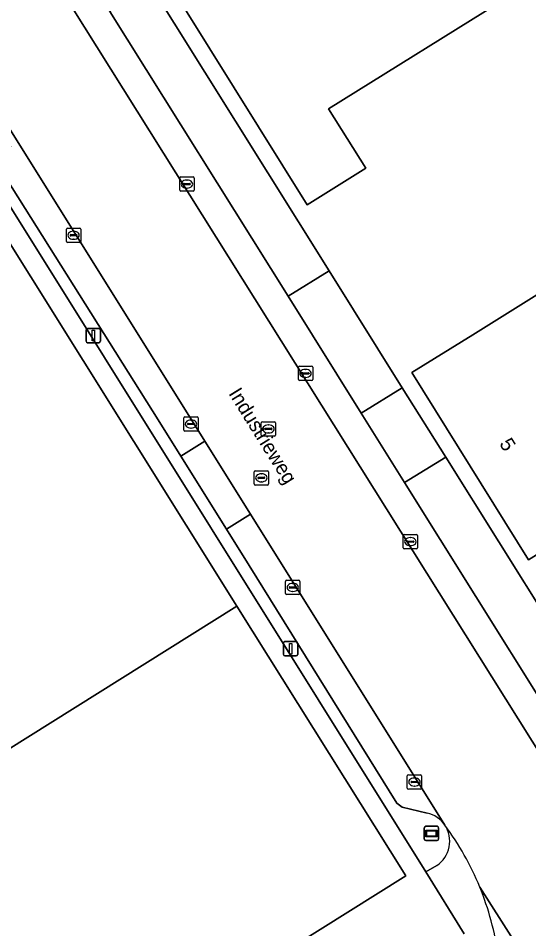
# Model space of a CAD drawing. Extents: x 158455 to 159797, y 387218 to 388672.
# Drawn here: x 158669.4 to 158705, y 387757.5 to 387821.1 of the extents above; entities that cross this region are included whole.
import ezdxf

# ---------------------------------------------------------------- set-up
doc = ezdxf.new("R2010")
doc.units = 0
for name, color, linetype in [('IMGEO_Erf', 7, 'Continuous'), ('IMGEO_Kolk', 7, 'Continuous'), ('IMGEO_Lichtmast', 7, 'Continuous'), ('IMGEO_Openbare_ruimte_label', 7, 'Continuous'), ('IMGEO_Pand', 7, 'Continuous'), ('IMGEO_Pand_nummerreeks', 7, 'Continuous'), ('IMGEO_Parkeervlak_open', 7, 'Continuous'), ('IMGEO_Rijbaan_lokaal_gesloten', 7, 'Continuous'), ('IMGEO_Rioolput', 7, 'Continuous'), ('IMGEO_Voetpad_open', 7, 'Continuous'), ('IMGEO_Wegwijzer', 7, 'Continuous')]:
    doc.layers.add(name, color=color, linetype=linetype)

msp = doc.modelspace()

# ---------------------------------------------------------------- linework, layer by layer
at = {"layer": 'IMGEO_Erf'}
for points in [[(158707.009, 387857.672), (158697.055, 387851.465), (158693.417, 387849.212), (158672.211, 387835.913), (158671.304, 387835.407), (158671.246, 387835.269), (158671.606, 387834.665), (158691.111, 387803.48), (158696.218, 387795.316), (158699.252, 387790.473), (158714.054, 387766.818), (158717.252, 387761.719), (158733.714, 387772.034), (158739.37, 387775.529), (158743.923, 387778.371), (158747.2, 387780.372), (158755.504, 387785.603)], [(158700.543, 387757.176), (158697.853, 387761.514), (158667.897, 387809.455), (158665.935, 387812.659), (158664.762, 387811.924), (158665.289, 387811.083), (158666.728, 387808.713), (158684.676, 387780.065), (158696.467, 387761.244), (158678.519, 387750)], [(158709.281, 387785.958), (158705.038, 387783.311), (158696.888, 387796.376), (158701.131, 387799.023), (158709.969, 387804.536)]]:
    msp.add_lwpolyline(points, dxfattribs=at)
msp.add_lwpolyline([(158694.061, 387848.221), (158704.182, 387854.586), (158709.488, 387846.148), (158713.329, 387848.544), (158722.022, 387834.609), (158708.006, 387825.866), (158703.715, 387823.19), (158703.941, 387822.828), (158691.073, 387814.801), (158693.667, 387810.644), (158689.585, 387808.098), (158672.704, 387835.159), (158689.655, 387845.732), (158689.781, 387845.53)], close=True, dxfattribs=at)
at = {"layer": 'IMGEO_Kolk'}
for p, q in [((158680.681, 387809.113), (158680.681, 387809.965)), ((158680.756, 387810.039), (158681.608, 387810.039)), ((158681.682, 387809.965), (158681.682, 387809.113)), ((158680.94, 387809.533), (158680.94, 387809.545)), ((158681.378, 387809.496), (158680.98, 387809.496)), ((158680.983, 387809.582), (158681.381, 387809.582)), ((158681.169, 387809.819), (158681.194, 387809.819)), ((158681.424, 387809.545), (158681.424, 387809.533)), ((158681.608, 387809.039), (158680.756, 387809.039)), ((158681.192, 387809.259), (158681.167, 387809.259)), ((158672.768, 387805.542), (158672.768, 387806.394)), ((158672.843, 387806.468), (158673.695, 387806.468)), ((158673.256, 387806.248), (158673.281, 387806.248)), ((158673.769, 387806.394), (158673.769, 387805.542)), ((158673.027, 387805.962), (158673.027, 387805.974)), ((158673.465, 387805.925), (158673.067, 387805.925)), ((158673.07, 387806.011), (158673.468, 387806.011)), ((158673.279, 387805.688), (158673.254, 387805.688)), ((158673.511, 387805.974), (158673.511, 387805.962)), ((158673.695, 387805.468), (158672.843, 387805.468)), ((158688.962, 387795.893), (158688.962, 387796.745)), ((158689.037, 387796.819), (158689.889, 387796.819)), ((158689.45, 387796.599), (158689.475, 387796.599)), ((158689.963, 387796.745), (158689.963, 387795.893)), ((158689.221, 387796.313), (158689.221, 387796.325)), ((158689.659, 387796.276), (158689.261, 387796.276)), ((158689.264, 387796.362), (158689.662, 387796.362)), ((158689.473, 387796.039), (158689.448, 387796.039)), ((158689.705, 387796.325), (158689.705, 387796.313)), ((158689.889, 387795.819), (158689.037, 387795.819)), ((158680.969, 387792.357), (158680.969, 387793.209)), ((158681.044, 387793.283), (158681.896, 387793.283)), ((158681.228, 387792.777), (158681.228, 387792.789)), ((158681.271, 387792.826), (158681.669, 387792.826)), ((158681.457, 387793.063), (158681.482, 387793.063)), ((158681.712, 387792.789), (158681.712, 387792.777)), ((158681.97, 387793.209), (158681.97, 387792.357)), ((158681.896, 387792.283), (158681.044, 387792.283)), ((158681.666, 387792.74), (158681.268, 387792.74)), ((158681.48, 387792.503), (158681.455, 387792.503)), ((158696.28, 387784.144), (158696.28, 387784.996)), ((158696.355, 387785.07), (158697.207, 387785.07)), ((158696.539, 387784.564), (158696.539, 387784.576)), ((158696.977, 387784.527), (158696.579, 387784.527)), ((158696.582, 387784.613), (158696.98, 387784.613)), ((158696.768, 387784.85), (158696.793, 387784.85)), ((158697.023, 387784.576), (158697.023, 387784.564)), ((158697.281, 387784.996), (158697.281, 387784.144)), ((158697.207, 387784.07), (158696.355, 387784.07)), ((158696.791, 387784.29), (158696.766, 387784.29)), ((158688.07, 387780.946), (158688.07, 387781.798)), ((158688.145, 387781.872), (158688.997, 387781.872)), ((158688.329, 387781.366), (158688.329, 387781.378)), ((158688.767, 387781.329), (158688.369, 387781.329)), ((158688.372, 387781.415), (158688.77, 387781.415)), ((158688.558, 387781.652), (158688.583, 387781.652)), ((158688.813, 387781.378), (158688.813, 387781.366)), ((158689.071, 387781.798), (158689.071, 387780.946)), ((158688.997, 387780.872), (158688.145, 387780.872)), ((158688.581, 387781.092), (158688.556, 387781.092)), ((158696.567, 387767.36), (158696.567, 387768.212)), ((158696.642, 387768.286), (158697.494, 387768.286)), ((158697.055, 387768.066), (158697.08, 387768.066)), ((158697.568, 387768.212), (158697.568, 387767.36)), ((158696.826, 387767.78), (158696.826, 387767.792)), ((158697.264, 387767.743), (158696.866, 387767.743)), ((158696.869, 387767.829), (158697.267, 387767.829)), ((158697.078, 387767.506), (158697.053, 387767.506)), ((158697.31, 387767.792), (158697.31, 387767.78)), ((158697.494, 387767.286), (158696.642, 387767.286))]:
    msp.add_line(p, q, dxfattribs=at)
for points in [[(158680.681, 387809.113), (158680.681, 387809.965)], [(158680.756, 387810.039), (158681.608, 387810.039)], [(158681.682, 387809.965), (158681.682, 387809.113)], [(158681.608, 387809.039), (158680.756, 387809.039)], [(158672.768, 387805.542), (158672.768, 387806.394)], [(158672.843, 387806.468), (158673.695, 387806.468)], [(158673.769, 387806.394), (158673.769, 387805.542)], [(158673.695, 387805.468), (158672.843, 387805.468)], [(158688.962, 387795.893), (158688.962, 387796.745)], [(158689.037, 387796.819), (158689.889, 387796.819)], [(158689.963, 387796.745), (158689.963, 387795.893)], [(158689.889, 387795.819), (158689.037, 387795.819)], [(158680.969, 387792.357), (158680.969, 387793.209)], [(158681.044, 387793.283), (158681.896, 387793.283)], [(158681.97, 387793.209), (158681.97, 387792.357)], [(158681.896, 387792.283), (158681.044, 387792.283)], [(158696.28, 387784.144), (158696.28, 387784.996)], [(158696.355, 387785.07), (158697.207, 387785.07)], [(158697.281, 387784.996), (158697.281, 387784.144)], [(158697.207, 387784.07), (158696.355, 387784.07)], [(158688.07, 387780.946), (158688.07, 387781.798)], [(158688.145, 387781.872), (158688.997, 387781.872)], [(158689.071, 387781.798), (158689.071, 387780.946)], [(158688.997, 387780.872), (158688.145, 387780.872)], [(158696.567, 387767.36), (158696.567, 387768.212)], [(158696.642, 387768.286), (158697.494, 387768.286)], [(158697.568, 387768.212), (158697.568, 387767.36)], [(158697.494, 387767.286), (158696.642, 387767.286)]]:
    msp.add_lwpolyline(points, dxfattribs=at)
for centre, radius, start, end in [((158680.758, 387809.963), 0.0765, 91.55205, 178.44795), ((158680.758, 387809.963), 0.0765, 91.55205, 178.44795), ((158681.606, 387809.963), 0.0765, 1.55205, 88.44795), ((158681.606, 387809.963), 0.0765, 1.55205, 88.44795), ((158680.98, 387809.542), 0.0403, 85.87752, 175.75265), ((158680.977, 387809.532), 0.0366, 178.93798, 274.71019), ((158681.381, 387809.539), 0.043, 264.86636, 352.45326), ((158681.385, 387809.544), 0.0386, 1.73085, 96.63898), ((158680.758, 387809.115), 0.0765, 181.55205, 268.44795), ((158680.758, 387809.115), 0.0765, 181.55205, 268.44795), ((158681.606, 387809.115), 0.0765, 271.55205, 358.44795), ((158681.606, 387809.115), 0.0765, 271.55205, 358.44795), ((158672.845, 387806.392), 0.0765, 91.55205, 178.44795), ((158672.845, 387806.392), 0.0765, 91.55205, 178.44795), ((158673.693, 387806.392), 0.0765, 1.55205, 88.44795), ((158673.693, 387806.392), 0.0765, 1.55205, 88.44795), ((158672.845, 387805.544), 0.0765, 181.55205, 268.44795), ((158672.845, 387805.544), 0.0765, 181.55205, 268.44795), ((158673.067, 387805.971), 0.0403, 85.87752, 175.75265), ((158673.064, 387805.961), 0.0366, 178.93798, 274.71019), ((158673.468, 387805.968), 0.043, 264.86636, 352.45326), ((158673.472, 387805.973), 0.0386, 1.73085, 96.63898), ((158673.693, 387805.544), 0.0765, 271.55205, 358.44795), ((158673.693, 387805.544), 0.0765, 271.55205, 358.44795), ((158689.039, 387796.743), 0.0765, 91.55205, 178.44795), ((158689.039, 387796.743), 0.0765, 91.55205, 178.44795), ((158689.887, 387796.743), 0.0765, 1.55205, 88.44795), ((158689.887, 387796.743), 0.0765, 1.55205, 88.44795), ((158689.261, 387796.322), 0.0403, 85.87752, 175.75265), ((158689.258, 387796.312), 0.0366, 178.93798, 274.71019), ((158689.662, 387796.319), 0.043, 264.86636, 352.45326), ((158689.666, 387796.324), 0.0386, 1.73085, 96.63898), ((158689.039, 387795.895), 0.0765, 181.55205, 268.44795), ((158689.039, 387795.895), 0.0765, 181.55205, 268.44795), ((158689.887, 387795.895), 0.0765, 271.55205, 358.44795), ((158689.887, 387795.895), 0.0765, 271.55205, 358.44795), ((158681.046, 387793.207), 0.0765, 91.55205, 178.44795), ((158681.046, 387793.207), 0.0765, 91.55205, 178.44795), ((158681.268, 387792.786), 0.0403, 85.87752, 175.75265), ((158681.265, 387792.776), 0.0366, 178.93798, 274.71019), ((158681.669, 387792.783), 0.043, 264.86636, 352.45326), ((158681.673, 387792.788), 0.0386, 1.73085, 96.63898), ((158681.894, 387793.207), 0.0765, 1.55205, 88.44795), ((158681.894, 387793.207), 0.0765, 1.55205, 88.44795), ((158681.046, 387792.359), 0.0765, 181.55205, 268.44795), ((158681.046, 387792.359), 0.0765, 181.55205, 268.44795), ((158681.894, 387792.359), 0.0765, 271.55205, 358.44795), ((158681.894, 387792.359), 0.0765, 271.55205, 358.44795), ((158696.357, 387784.994), 0.0765, 91.55205, 178.44795), ((158696.357, 387784.994), 0.0765, 91.55205, 178.44795), ((158696.579, 387784.573), 0.0403, 85.87752, 175.75265), ((158696.576, 387784.563), 0.0366, 178.93798, 274.71019), ((158696.98, 387784.57), 0.043, 264.86636, 352.45326), ((158696.984, 387784.575), 0.0386, 1.73085, 96.63898), ((158697.205, 387784.994), 0.0765, 1.55205, 88.44795), ((158697.205, 387784.994), 0.0765, 1.55205, 88.44795), ((158696.357, 387784.146), 0.0765, 181.55205, 268.44795), ((158696.357, 387784.146), 0.0765, 181.55205, 268.44795), ((158697.205, 387784.146), 0.0765, 271.55205, 358.44795), ((158697.205, 387784.146), 0.0765, 271.55205, 358.44795), ((158688.147, 387781.796), 0.0765, 91.55205, 178.44795), ((158688.147, 387781.796), 0.0765, 91.55205, 178.44795), ((158688.369, 387781.375), 0.0403, 85.87752, 175.75265), ((158688.366, 387781.365), 0.0366, 178.93798, 274.71019), ((158688.77, 387781.372), 0.043, 264.86636, 352.45326), ((158688.774, 387781.377), 0.0386, 1.73085, 96.63898), ((158688.995, 387781.796), 0.0765, 1.55205, 88.44795), ((158688.995, 387781.796), 0.0765, 1.55205, 88.44795), ((158688.147, 387780.948), 0.0765, 181.55205, 268.44795), ((158688.147, 387780.948), 0.0765, 181.55205, 268.44795), ((158688.995, 387780.948), 0.0765, 271.55205, 358.44795), ((158688.995, 387780.948), 0.0765, 271.55205, 358.44795), ((158696.644, 387768.21), 0.0765, 91.55205, 178.44795), ((158696.644, 387768.21), 0.0765, 91.55205, 178.44795), ((158697.492, 387768.21), 0.0765, 1.55205, 88.44795), ((158697.492, 387768.21), 0.0765, 1.55205, 88.44795), ((158696.644, 387767.362), 0.0765, 181.55205, 268.44795), ((158696.644, 387767.362), 0.0765, 181.55205, 268.44795), ((158696.866, 387767.789), 0.0403, 85.87752, 175.75265), ((158696.863, 387767.779), 0.0366, 178.93798, 274.71019), ((158697.267, 387767.786), 0.043, 264.86636, 352.45326), ((158697.271, 387767.791), 0.0386, 1.73085, 96.63898), ((158697.492, 387767.362), 0.0765, 271.55205, 358.44795), ((158697.492, 387767.362), 0.0765, 271.55205, 358.44795)]:
    msp.add_arc(centre, radius, start, end, dxfattribs=at)
for centre, major_axis, ratio, start_param, end_param in [((158681.168, 387809.539), (-0.387, 0.002), 0.722429, 4.712389, 7.853982), ((158681.193, 387809.539), (-0.39, 0.002), 0.717154, 1.570796, 4.712389), ((158673.255, 387805.968), (-0.387, 0.002), 0.722429, 4.712389, 7.853982), ((158673.28, 387805.968), (-0.39, 0.002), 0.717154, 1.570796, 4.712389), ((158689.449, 387796.319), (-0.387, 0.002), 0.722429, 4.712389, 7.853982), ((158689.474, 387796.319), (-0.39, 0.002), 0.717154, 1.570796, 4.712389), ((158681.456, 387792.783), (-0.387, 0.002), 0.722429, 4.712389, 7.853982), ((158681.481, 387792.783), (-0.39, 0.002), 0.717154, 1.570796, 4.712389), ((158696.767, 387784.57), (-0.387, 0.002), 0.722429, 4.712389, 7.853982), ((158696.792, 387784.57), (-0.39, 0.002), 0.717154, 1.570796, 4.712389), ((158688.557, 387781.372), (-0.387, 0.002), 0.722429, 4.712389, 7.853982), ((158688.582, 387781.372), (-0.39, 0.002), 0.717154, 1.570796, 4.712389), ((158697.054, 387767.786), (-0.387, 0.002), 0.722429, 4.712389, 7.853982), ((158697.079, 387767.786), (-0.39, 0.002), 0.717154, 1.570796, 4.712389)]:
    msp.add_ellipse(centre, major_axis=major_axis, ratio=ratio, start_param=start_param, end_param=end_param, dxfattribs=at)
at = {"layer": 'IMGEO_Lichtmast'}
for p, q in [((158674.152, 387798.561), (158674.152, 387799.361)), ((158674.152, 387799.361), (158674.152, 387798.561)), ((158674.252, 387799.461), (158675.042, 387799.461)), ((158675.042, 387799.461), (158674.252, 387799.461)), ((158675.142, 387799.361), (158675.142, 387798.561)), ((158675.142, 387798.561), (158675.142, 387799.361)), ((158675.042, 387798.461), (158674.252, 387798.461)), ((158674.252, 387798.461), (158675.042, 387798.461)), ((158688.025, 387777.588), (158688.815, 387777.588)), ((158688.815, 387777.588), (158688.025, 387777.588)), ((158687.925, 387776.688), (158687.925, 387777.488)), ((158687.925, 387777.488), (158687.925, 387776.688)), ((158688.915, 387777.488), (158688.915, 387776.688)), ((158688.915, 387776.688), (158688.915, 387777.488)), ((158688.815, 387776.588), (158688.025, 387776.588)), ((158688.025, 387776.588), (158688.815, 387776.588))]:
    msp.add_line(p, q, dxfattribs=at)
for points in [[(158674.572, 387799.336), (158674.722, 387799.336), (158674.722, 387798.586), (158674.572, 387798.586), (158674.572, 387799.336)], [(158688.345, 387777.463), (158688.495, 387777.463), (158688.495, 387776.713), (158688.345, 387776.713), (158688.345, 387777.463)]]:
    msp.add_lwpolyline(points, dxfattribs=at)
for centre, start, end in [((158674.252, 387799.361), 90, 180), ((158674.252, 387799.361), 90, 180), ((158675.042, 387799.361), 0, 90), ((158675.042, 387799.361), 360, 90), ((158674.252, 387798.561), 180, 270), ((158674.252, 387798.561), 180, 270), ((158675.042, 387798.561), 270, 0), ((158675.042, 387798.561), 270, 0), ((158688.025, 387777.488), 90, 180), ((158688.025, 387777.488), 90, 180), ((158688.815, 387777.488), 0, 90), ((158688.815, 387777.488), 360, 90), ((158688.025, 387776.688), 180, 270), ((158688.025, 387776.688), 180, 270), ((158688.815, 387776.688), 270, 0), ((158688.815, 387776.688), 270, 0)]:
    msp.add_arc(centre, 0.1, start, end, dxfattribs=at)
at = {"layer": 'IMGEO_Pand'}
for points in [[(158708.006, 387825.866), (158699.23, 387839.95), (158694.061, 387848.221), (158689.781, 387845.53), (158689.655, 387845.732), (158672.704, 387835.159), (158689.585, 387808.098), (158693.667, 387810.644), (158691.073, 387814.801), (158703.941, 387822.828), (158703.715, 387823.19)], [(158718.906, 387808.438), (158715.842, 387813.35), (158714.709, 387815.167), (158709.613, 387811.988), (158711.297, 387809.289), (158708.207, 387807.361), (158709.969, 387804.536), (158701.131, 387799.023), (158696.888, 387796.376), (158705.038, 387783.311), (158709.281, 387785.958), (158724.907, 387795.706), (158719.499, 387804.377), (158720.877, 387805.237), (158719.649, 387807.206)], [(158666.728, 387808.713), (158665.888, 387808.187), (158661.989, 387809.082), (158661.505, 387809.854), (158651.443, 387803.55), (158647.008, 387800.772), (158666.776, 387768.852), (158666.941, 387768.955), (158684.676, 387780.065)], [(158649.189, 387757.833), (158654.096, 387750), (158658.943, 387742.264), (158659.793, 387742.796), (158663.673, 387741.904), (158664.215, 387741.039), (158678.519, 387750), (158696.467, 387761.244), (158684.676, 387780.065), (158666.941, 387768.955), (158666.776, 387768.852)]]:
    msp.add_lwpolyline(points, close=True, dxfattribs=at)
at = {"layer": 'IMGEO_Parkeervlak_open'}
for points in [[(158672.195, 387823.443), (158707.993, 387766.325)], [(158711.804, 387763.653), (158711.846, 387763.835), (158711.756, 387764.131), (158711.195, 387765.014), (158696.373, 387788.699), (158693.355, 387793.532), (158688.249, 387801.704), (158675.809, 387821.598), (158675.707, 387821.76)], [(158668.857, 387812.187), (158668.512, 387810.397), (158668.593, 387809.918), (158679.183, 387793.077), (158680.765, 387790.537), (158682.44, 387791.58), (158668.626, 387813.681)], [(158685.624, 387786.486), (158683.942, 387785.438), (158685.524, 387782.898), (158695.827, 387766.313), (158696.197, 387766.018), (158697.954, 387765.62)], [(158699.196, 387764.771), (158685.624, 387786.486)]]:
    msp.add_lwpolyline(points, dxfattribs=at)
msp.add_lwpolyline([(158682.44, 387791.58), (158680.765, 387790.537), (158683.942, 387785.438), (158685.624, 387786.486)], close=True, dxfattribs=at)
msp.add_arc((158697.531, 387763.669), 1.996, 33.50856, 77.78037, dxfattribs=at)
at = {"layer": 'IMGEO_Rijbaan_lokaal_gesloten'}
for points in [[(158648.193, 387847.22), (158648.302, 387847.052), (158663.777, 387821.236), (158668.626, 387813.681), (158682.44, 387791.58), (158685.624, 387786.486), (158699.196, 387764.771)], [(158701.625, 387760.45), (158716.254, 387737.492), (158717.377, 387735.852), (158725.058, 387738.734), (158724.913, 387738.934), (158707.993, 387766.325), (158672.195, 387823.443), (158671.961, 387823.816)], [(158716.254, 387737.492), (158701.625, 387760.45)]]:
    msp.add_lwpolyline(points, dxfattribs=at)
for centre, radius, start, end in [((158683.02, 387752.835), 20.103, 22.25999, 36.42404), ((158682.951, 387752.811), 20.176, 8.13464, 22.24787)]:
    msp.add_arc(centre, radius, start, end, dxfattribs=at)
at = {"layer": 'IMGEO_Rioolput'}
for p, q in [((158686.374, 387792.017), (158686.374, 387792.869)), ((158686.449, 387792.943), (158687.301, 387792.943)), ((158687.375, 387792.869), (158687.375, 387792.017)), ((158686.633, 387792.437), (158686.633, 387792.449)), ((158687.071, 387792.4), (158686.673, 387792.4)), ((158686.676, 387792.486), (158687.074, 387792.486)), ((158686.885, 387792.163), (158686.86, 387792.163)), ((158686.862, 387792.723), (158686.887, 387792.723)), ((158687.117, 387792.449), (158687.117, 387792.437)), ((158687.301, 387791.943), (158686.449, 387791.943)), ((158685.879, 387788.6), (158685.879, 387789.452)), ((158685.954, 387789.526), (158686.806, 387789.526)), ((158686.138, 387789.02), (158686.138, 387789.032)), ((158686.576, 387788.983), (158686.178, 387788.983)), ((158686.181, 387789.069), (158686.579, 387789.069)), ((158686.367, 387789.306), (158686.392, 387789.306)), ((158686.622, 387789.032), (158686.622, 387789.02)), ((158686.88, 387789.452), (158686.88, 387788.6)), ((158686.806, 387788.526), (158685.954, 387788.526)), ((158686.39, 387788.746), (158686.365, 387788.746))]:
    msp.add_line(p, q, dxfattribs=at)
for points in [[(158686.374, 387792.017), (158686.374, 387792.869)], [(158686.449, 387792.943), (158687.301, 387792.943)], [(158687.375, 387792.869), (158687.375, 387792.017)], [(158687.301, 387791.943), (158686.449, 387791.943)], [(158685.879, 387788.6), (158685.879, 387789.452)], [(158685.954, 387789.526), (158686.806, 387789.526)], [(158686.88, 387789.452), (158686.88, 387788.6)], [(158686.806, 387788.526), (158685.954, 387788.526)]]:
    msp.add_lwpolyline(points, dxfattribs=at)
for centre, radius, start, end in [((158686.451, 387792.867), 0.0765, 91.55205, 178.44795), ((158686.451, 387792.867), 0.0765, 91.55205, 178.44795), ((158687.299, 387792.867), 0.0765, 1.55205, 88.44795), ((158687.299, 387792.867), 0.0765, 1.55205, 88.44795), ((158686.673, 387792.446), 0.0403, 85.87752, 175.75265), ((158686.67, 387792.436), 0.0366, 178.93798, 274.71019), ((158687.074, 387792.443), 0.043, 264.86636, 352.45326), ((158687.078, 387792.448), 0.0386, 1.73085, 96.63898), ((158686.451, 387792.019), 0.0765, 181.55205, 268.44795), ((158686.451, 387792.019), 0.0765, 181.55205, 268.44795), ((158687.299, 387792.019), 0.0765, 271.55205, 358.44795), ((158687.299, 387792.019), 0.0765, 271.55205, 358.44795), ((158685.956, 387789.45), 0.0765, 91.55205, 178.44795), ((158685.956, 387789.45), 0.0765, 91.55205, 178.44795), ((158686.178, 387789.029), 0.0403, 85.87752, 175.75265), ((158686.175, 387789.019), 0.0366, 178.93798, 274.71019), ((158686.579, 387789.026), 0.043, 264.86636, 352.45326), ((158686.583, 387789.031), 0.0386, 1.73085, 96.63898), ((158686.804, 387789.45), 0.0765, 1.55205, 88.44795), ((158686.804, 387789.45), 0.0765, 1.55205, 88.44795), ((158685.956, 387788.602), 0.0765, 181.55205, 268.44795), ((158685.956, 387788.602), 0.0765, 181.55205, 268.44795), ((158686.804, 387788.602), 0.0765, 271.55205, 358.44795), ((158686.804, 387788.602), 0.0765, 271.55205, 358.44795)]:
    msp.add_arc(centre, radius, start, end, dxfattribs=at)
for centre, major_axis, ratio, start_param, end_param in [((158686.861, 387792.443), (-0.387, 0.002), 0.722429, 4.712389, 7.853982), ((158686.886, 387792.443), (-0.39, 0.002), 0.717154, 1.570796, 4.712389), ((158686.366, 387789.026), (-0.387, 0.002), 0.722429, 4.712389, 7.853982), ((158686.391, 387789.026), (-0.39, 0.002), 0.717154, 1.570796, 4.712389)]:
    msp.add_ellipse(centre, major_axis=major_axis, ratio=ratio, start_param=start_param, end_param=end_param, dxfattribs=at)
at = {"layer": 'IMGEO_Voetpad_open'}
for points in [[(158676.299, 387821.874), (158675.809, 387821.598), (158688.249, 387801.704), (158691.111, 387803.48), (158671.606, 387834.665)], [(158665.962, 387813.837), (158665.421, 387813.498), (158665.935, 387812.659), (158667.897, 387809.455), (158697.853, 387761.514), (158698.622, 387761.964)], [(158697.954, 387765.62), (158696.197, 387766.018), (158695.827, 387766.313), (158685.524, 387782.898), (158683.942, 387785.438), (158680.765, 387790.537), (158679.183, 387793.077), (158668.593, 387809.918)], [(158698.622, 387761.964), (158697.853, 387761.514), (158700.543, 387757.176)]]:
    msp.add_lwpolyline(points, dxfattribs=at)
for points in [[(158693.355, 387793.532), (158696.218, 387795.316), (158691.111, 387803.48), (158688.249, 387801.704)], [(158699.252, 387790.473), (158696.218, 387795.316), (158693.355, 387793.532), (158696.373, 387788.699)], [(158711.195, 387765.014), (158714.054, 387766.818), (158699.252, 387790.473), (158696.373, 387788.699)]]:
    msp.add_lwpolyline(points, close=True, dxfattribs=at)
for centre, radius, start, end in [((158697.531, 387763.669), 1.996, 33.50856, 77.78037), ((158697.507, 387763.654), 2.025, 303.40461, 33.48136), ((158697.507, 387763.654), 2.025, 303.40461, 33.48136), ((158683.02, 387752.835), 20.103, 22.25999, 36.42404), ((158682.951, 387752.811), 20.176, 8.13464, 22.24787)]:
    msp.add_arc(centre, radius, start, end, dxfattribs=at)
at = {"layer": 'IMGEO_Wegwijzer'}
for p, q in [((158697.751, 387763.793), (158697.751, 387764.593)), ((158697.751, 387764.593), (158697.751, 387763.793)), ((158697.851, 387764.693), (158698.641, 387764.693)), ((158698.641, 387764.693), (158697.851, 387764.693)), ((158698.741, 387764.593), (158698.741, 387763.793)), ((158698.741, 387763.793), (158698.741, 387764.593)), ((158698.641, 387763.693), (158697.851, 387763.693)), ((158697.851, 387763.693), (158698.641, 387763.693))]:
    msp.add_line(p, q, dxfattribs=at)
for points in [[(158697.852, 387764.425), (158698.64, 387764.425), (158698.64, 387763.961), (158697.852, 387763.961), (158697.852, 387764.425)], [(158697.917, 387764.36), (158697.917, 387764.026), (158698.575, 387764.026), (158698.575, 387764.36), (158697.917, 387764.36)]]:
    msp.add_lwpolyline(points, dxfattribs=at)
for centre, start, end in [((158697.851, 387764.593), 90, 180), ((158697.851, 387764.593), 90, 180), ((158698.641, 387764.593), 0, 90), ((158698.641, 387764.593), 360, 90), ((158697.851, 387763.793), 180, 270), ((158697.851, 387763.793), 180, 270), ((158698.641, 387763.793), 270, 0), ((158698.641, 387763.793), 270, 0)]:
    msp.add_arc(centre, 0.1, start, end, dxfattribs=at)

# ---------------------------------------------------------------- texts
at = {"layer": 'IMGEO_Openbare_ruimte_label'}
msp.add_text('Industrieweg', height=1, rotation=301.92646, dxfattribs=at).set_placement((158684.055, 387794.922))
at = {"layer": 'IMGEO_Pand_nummerreeks'}
msp.add_text('5', height=1, rotation=301.95608, dxfattribs=at).set_placement((158702.956, 387791.411))

doc.saveas('drawing.dxf')
